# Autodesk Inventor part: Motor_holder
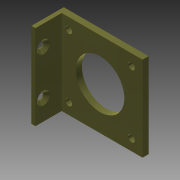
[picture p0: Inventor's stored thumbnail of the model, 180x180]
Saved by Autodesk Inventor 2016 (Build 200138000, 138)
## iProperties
Created: 2014-07
Part Number: Motor_holder
Material: Titanium
Document SubType Name: Modeling
Designer: James
Density: 4.51 g/cm^3
Appearance: Titanium
Author: James
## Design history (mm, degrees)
sketch "Sketch1"
  geometry: L1 (0, 24.391)-(16, 24.391); L2 (16, 24.391)-(16, -17.609); L3 (16, -17.609)-(0, -17.609); L4 (0, -17.609)-(0, 24.391); 1 further point
  constraints: 8 end point, 2 parallel, 1 horizontal, 1 perpendicular
  dimensions: "d0" = 42 distance between parallel lines of L3 L1; "d1" = 16 distance between parallel lines of L2 L4
extrude "Extrusion1" new body sketch "Sketch1" distance "d2" = 2; taper "d3" = 0 deg
sketch "Sketch2"
  geometry: L1 (17.609, 0)-(17.609, 16) reference; L2 (17.609, 16)-(-24.391, 16) reference; L3 (-24.391, 16)-(17.609, 16); L4 (17.609, 16)-(17.609, 13); L5 (17.609, 13)-(-24.391, 13); L6 (-24.391, 13)-(-24.391, 16); 1 further point
  constraints: 8 end point, 2 parallel, 1 horizontal, 1 perpendicular, 1 point on line
  dimensions: "d4" = 3 distance between parallel lines of L3 L5
extrude "Extrusion2" join sketch "Sketch2" distance "d5" = 40; taper "d6" = 0 deg
sketch "Sketch3"
  geometry: L1 (0, 42)-(42, 42) reference; L2 (36.5, 36.5)-(36.5, 5.5); L3 (36.5, 5.5)-(5.5, 5.5); L4 (5.5, 5.5)-(5.5, 36.5); L5 (5.5, 36.5)-(36.5, 36.5); L6 (0, 0)-(42, 0) reference; L7 (42, 42)-(42, 0) reference; 6 further points
  constraints: 8 end point, 4 coincident, 9 other
  dimensions: "d7" = 31 distance between parallel lines of L4 L2; "d8" = 0 deg angle of L1 L5; "d32" = 5.49974 distance from line of L7 point (36.5, 36.5); "d33" = 5.5 distance from line of L1 point (36.5, 36.5); "d34" = 5.5 distance from line of L1 L4.end (derived); "d35" = 5.5 distance from line of L6 point (5.5, 5.5) (derived); "d36" = 5.49974 distance from line of L7 L2.end (derived)
hole "Hole1" sketch "Sketch3" at (5.5, 36.5), (36.5, 36.5), (36.5, 5.5), (5.5, 5.5) diameter "d9" = 3.2; stored, may be unused: countersink angle "d13" = 90 deg, drill point angle "d15" = 118 deg; dims "d10" = 6, "d11" = 6.5, "d12" = 3, "d14" = 8
sketch "Sketch4"
  geometry: L1 (-24.391, 13)-(-24.391, 0) reference; L2 (17.609, 0)-(17.609, 13) reference; 3 further points
  dimensions: "d16" = 10 distance from line of L2 point (7.609, 4); "d17" = 10 distance from line of L1 point (-14.391, 4) (= d16)
hole "Hole2" sketch "Sketch4" at (-14.391, 4), (7.609, 4) diameter "d18" = 3.2; stored, may be unused: countersink angle "d22" = 90 deg, drill point angle "d24" = 118 deg; dims "d19" = 6, "d20" = 6.3, "d21" = 3, "d23" = 8
sketch "Sketch5"
  geometry: 2 further points
hole "Hole3" sketch "Sketch5" at (21, 21) diameter "d25" = 24; stored, may be unused: countersink angle "d29" = 90 deg, drill point angle "d31" = 118 deg; dims "d26" = 6, "d27" = 6.5, "d28" = 3, "d30" = 8
body "Solid1"
